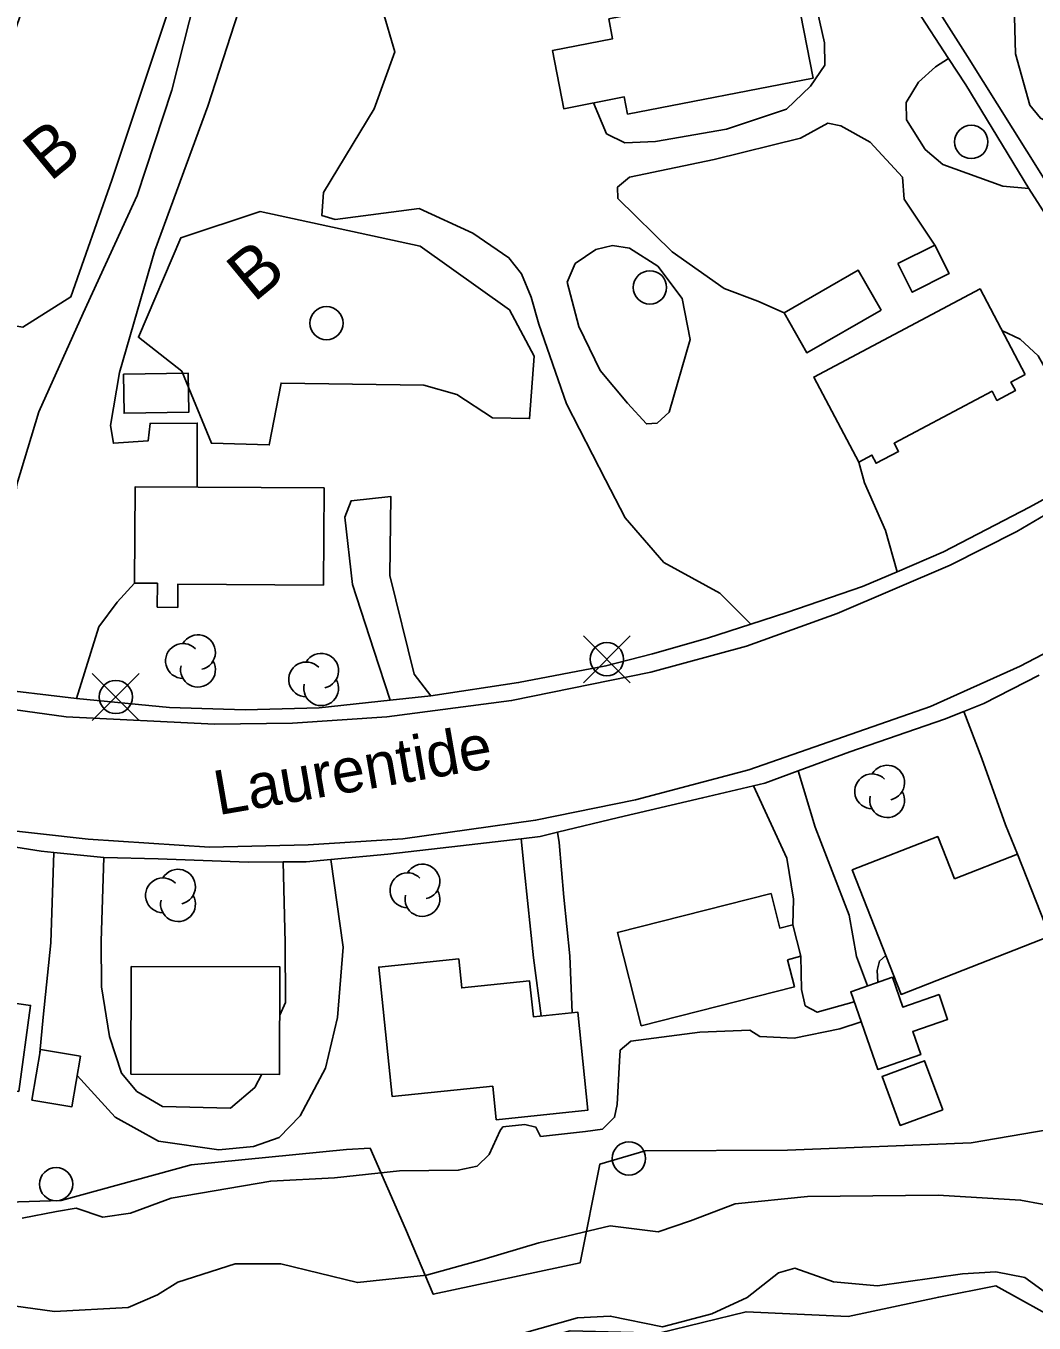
# Model space of a CAD drawing. Extents: x 347059 to 352153, y 6073752 to 6078601.
# Drawn here: x 348771.1 to 348862, y 6074348.3 to 6074465.1 of the extents above; entities that cross this region are included whole.
import ezdxf

# ---------------------------------------------------------------- set-up
doc = ezdxf.new("R2010")
doc.units = 0
for name, color, linetype in [('Level 19', 7, 'Continuous'), ('Level 2', 7, 'Continuous'), ('Level 21', 7, 'Continuous'), ('Level 22', 7, 'Continuous'), ('Level 31', 7, 'Continuous'), ('Level 36', 7, 'Continuous'), ('Level 4', 7, 'Continuous'), ('Level 44', 7, 'Continuous')]:
    doc.layers.add(name, color=color, linetype=linetype)

msp = doc.modelspace()

# ---------------------------------------------------------------- linework, layer by layer
at = {"layer": 'Level 19'}
for points in [[(348767.61, 6074405.52), (348768.93, 6074410.7), (348769.75, 6074418.56), (348770.34, 6074423.81), (348772.31, 6074430.38), (348776.32, 6074439.27), (348781.18, 6074449.85), (348784.3, 6074459.35), (348786.9, 6074469.69), (348789.29, 6074475.94), (348791.24, 6074483.88)], [(348838.96, 6074479.63), (348839.5, 6074478.19), (348840.93, 6074473.21), (348843.09, 6074463.63), (348843.12, 6074461.61), (348841.85, 6074459.71), (348839.66, 6074457.64), (348834.28, 6074455.83), (348827.86, 6074454.73), (348825.11, 6074454.61), (348823.47, 6074455.42), (348822.29, 6074458.2)], [(348903.21, 6074452.61), (348898.9, 6074457.29), (348893.63, 6074463.12), (348887.95, 6074467.63), (348883.19, 6074464.98), (348879.98, 6074463.79), (348874.86, 6074461.22), (348872.05, 6074459.46), (348865.53, 6074455.94), (348864.04, 6074456.12), (348862.55, 6074456.83), (348861.59, 6074457.99), (348860.3, 6074462.63), (348860.12, 6074469.35), (348860.79, 6074472.71)], [(348786.58, 6074423.58), (348786.58, 6074429.36), (348782.34, 6074429.33), (348782.16, 6074427.75), (348779.03, 6074427.54), (348778.78, 6074429.14), (348779.59, 6074433.92), (348782.76, 6074444.9), (348787.55, 6074457.92), (348791.33, 6074469.63)], [(348803.27, 6074466.6), (348804.4, 6074462.8), (348802.51, 6074457.66), (348797.97, 6074450.13), (348797.82, 6074448.05), (348799.01, 6074447.69), (348806.57, 6074448.69), (348811.4, 6074446.48), (348814.67, 6074444.25), (348815.8, 6074442.79), (348816.68, 6074440.71), (348817.36, 6074438.27), (348819.86, 6074431.09), (348823.37, 6074424.23), (348825.15, 6074420.82), (348828.63, 6074416.8), (348833.68, 6074414.04), (348836.45, 6074411.24)], [(348861.52, 6074450.49), (348859.17, 6074450.7), (348853.75, 6074452.64), (348852.16, 6074454.02), (348850.48, 6074456.68), (348850.46, 6074458.25), (348851.56, 6074460.08), (348853.11, 6074461.46), (348854.27, 6074462.21)], [(348839.45, 6074439.3), (348837.09, 6074440.33), (348834.05, 6074441.48), (348829.37, 6074444.78), (348824.49, 6074449.59), (348824.46, 6074450.62), (348825.52, 6074451.51), (348833.17, 6074453.11), (348840.93, 6074455.04), (348843.41, 6074456.37), (348844.58, 6074456.14), (348847.22, 6074454.67), (348850.12, 6074451.52), (348850.27, 6074449.54), (348853.03, 6074445.4)], [(348819.9, 6074442.06), (348820.97, 6074438.06), (348822.9, 6074434.1), (348825.34, 6074431.16), (348827.05, 6074429.28), (348828.03, 6074429.36), (348829.1, 6074430.33), (348830.99, 6074436.9), (348830.26, 6074440.59), (348828.07, 6074443.5), (348825.52, 6074445.13), (348823.99, 6074445.35), (348822.49, 6074445), (348820.62, 6074443.73), (348819.9, 6074442.06)], [(348859.09, 6074437.7), (348860.72, 6074436.92), (348862.34, 6074435.42), (348865.54, 6074429.74), (348867.91, 6074425.47)], [(348849.64, 6074415.96), (348848.59, 6074419.68), (348846.69, 6074423.96), (348846.18, 6074425.85)], [(348807.62, 6074404.77), (348806.13, 6074406.75), (348803.94, 6074415.62), (348804.04, 6074422.73), (348800.45, 6074422.36), (348799.87, 6074420.89), (348800.56, 6074414.82), (348802.48, 6074408.89), (348803.98, 6074404.38)], [(348775.69, 6074404.54), (348777.73, 6074411.01), (348779.36, 6074413.21), (348780.94, 6074414.95)], [(348855.65, 6074403.38), (348857.28, 6074399.13), (348859.4, 6074393.15), (348860.49, 6074390.53)], [(348840.74, 6074398.03), (348842.27, 6074392.94), (348845.31, 6074385.02), (348845.99, 6074381.3), (348846.97, 6074378.65)], [(348840.26, 6074384.16), (348840.3, 6074386.46), (348839.69, 6074390.17), (348836.71, 6074396.68)], [(348815.76, 6074391.91), (348816.08, 6074388.93), (348816.89, 6074381.17), (348817.57, 6074375.95)], [(348820.37, 6074376.24), (348820.14, 6074381.35), (348819.6, 6074386.64), (348819.18, 6074391.57), (348819.04, 6074392.49)], [(348773.66, 6074390.68), (348773.38, 6074382.52), (348772.71, 6074375.84), (348772.41, 6074372.63)], [(348775.77, 6074370.58), (348779.19, 6074366.82), (348783.08, 6074364.66), (348788.52, 6074363.88), (348791.65, 6074364.18), (348793.96, 6074364.99), (348795.85, 6074366.96), (348798.15, 6074371.23), (348799.21, 6074375.82), (348799.73, 6074382.14), (348798.61, 6074390.04)], [(348778.18, 6074390.21), (348777.92, 6074382.67), (348777.97, 6074378.56), (348778.67, 6074374.1), (348779.77, 6074370.79), (348781.13, 6074369.15), (348783.46, 6074367.79), (348789.57, 6074367.65), (348791.78, 6074369.5), (348792.41, 6074370.69)], [(348794.31, 6074389.82), (348794.51, 6074382.52), (348794.55, 6074377.16), (348794.01, 6074376.03)], [(348845.78, 6074377.21), (348842.44, 6074376.28), (348841.35, 6074376.87), (348841.03, 6074378.34), (348840.98, 6074381.32)]]:
    msp.add_lwpolyline(points, dxfattribs=at)
at = {"layer": 'Level 2'}
for points in [[(348860.74, 6074389.88), (348860.72, 6074389.87)], [(348848.62, 6074381.4), (348848.05, 6074380.89), (348847.83, 6074380.04), (348847.91, 6074378.98)], [(348846.4, 6074375.42), (348844.48, 6074374.77), (348840.37, 6074373.95), (348837.26, 6074374.08), (348836.37, 6074374.67), (348831.87, 6074374.49), (348825.64, 6074373.66), (348824.7, 6074372.87), (348824.62, 6074371.86), (348824.43, 6074367.96), (348824.19, 6074366.82), (348823.09, 6074365.76), (348821.55, 6074365.53), (348817.52, 6074365.09), (348817.09, 6074365.92), (348816.09, 6074366.16), (348814.12, 6074365.97), (348813.88, 6074365.63), (348812.9, 6074363.46), (348811.79, 6074362.4), (348810.1, 6074362.04), (348804.8, 6074362), (348798.95, 6074361.36), (348793.2, 6074361.07), (348784.23, 6074359.54), (348780.57, 6074358.19), (348778.07, 6074357.83), (348775.68, 6074358.62), (348773.91, 6074358.34), (348770.82, 6074357.74)], [(348912.02, 6074354.33), (348907.11, 6074355.41), (348904.58, 6074355.42), (348903.02, 6074355.05), (348899.24, 6074354), (348896.1, 6074352.03), (348893.13, 6074351.13), (348890.25, 6074351.38), (348888.9, 6074351.72), (348883.01, 6074354.93), (348877.78, 6074356.55), (348874.88, 6074357.32), (348866.62, 6074358.26), (348860.77, 6074359.36), (348853.34, 6074359.8), (348841.58, 6074359.67), (348835.06, 6074359.01), (348831.02, 6074357.48), (348828.11, 6074356.5), (348823.8, 6074357.03)], [(348768.27, 6074350.08), (348773.73, 6074349.31), (348780.36, 6074349.67), (348783, 6074350.82), (348784.84, 6074351.96), (348789.99, 6074353.62), (348794.12, 6074353.61), (348801.02, 6074351.92), (348807.24, 6074352.6), (348812.22, 6074353.98), (348817.36, 6074355.49), (348823.8, 6074357.03)]]:
    msp.add_lwpolyline(points, dxfattribs=at)
at = {"layer": 'Level 21'}
for points in [[(348767.35, 6074403.9), (348774.78, 6074402.9), (348788.15, 6074402.22), (348795.17, 6074402.32), (348803.67, 6074402.9), (348814.9, 6074404.35), (348827.45, 6074406.91), (348836.06, 6074409.25), (348844.24, 6074412.21), (348854.42, 6074416.55), (348860.44, 6074419.58), (348870.13, 6074425.31), (348877.31, 6074430.29), (348887.9, 6074438.38), (348896.05, 6074445.08), (348904.85, 6074452.18), (348914.51, 6074459.85), (348923.26, 6074466.91)], [(348767.86, 6074392.86), (348776.75, 6074391.88), (348787.7, 6074391.14), (348796.58, 6074391.36), (348805.12, 6074391.9), (348817.06, 6074393.57), (348826.08, 6074395.43), (348836.27, 6074398.12), (348844.82, 6074401.08), (348852.65, 6074403.82), (348860.72, 6074407.45), (348870.22, 6074412.42)]]:
    msp.add_lwpolyline(points, dxfattribs=at)
at = {"layer": 'Level 22'}
for points in [[(348852.05, 6074468.6), (348855.98, 6074462.39), (348862.73, 6074451.61), (348870.28, 6074439.32), (348875.67, 6074430.81), (348879.74, 6074433.85), (348886.12, 6074438.62), (348893.49, 6074444.82), (348895.77, 6074446.67), (348899.3, 6074449.55), (348903.21, 6074452.61), (348905.79, 6074454.64), (348912.74, 6074460.34), (348920.82, 6074466.76)], [(348867.35, 6074441.36), (348861.52, 6074450.49), (348855.82, 6074459.82), (348854.27, 6074462.21), (348851.41, 6074466.6)], [(348767.61, 6074405.52), (348775.69, 6074404.54), (348784.07, 6074403.74), (348790.91, 6074403.53), (348797.57, 6074403.7), (348803.98, 6074404.38), (348807.62, 6074404.77), (348815.53, 6074405.98), (348823.41, 6074407.48), (348827.59, 6074408.58), (348832.57, 6074409.98), (348836.45, 6074411.24), (348839.71, 6074412.29), (348846.53, 6074414.63), (348849.64, 6074415.96), (348853.82, 6074417.75), (348861.56, 6074421.77), (348866.54, 6074424.53)], [(348766.77, 6074391.69), (348772.52, 6074390.8), (348773.66, 6074390.68), (348778.18, 6074390.21), (348783.07, 6074390.09), (348791.17, 6074389.81), (348794.31, 6074389.82), (348796.39, 6074389.83), (348798.61, 6074390.04), (348803.76, 6074390.52), (348810.31, 6074391.28), (348815.76, 6074391.91), (348817.48, 6074392.11), (348819.04, 6074392.49), (348824.53, 6074393.81), (348832.11, 6074395.59), (348836.71, 6074396.68), (348837.73, 6074396.93), (348840.74, 6074398.03), (348845.37, 6074399.73), (348853.91, 6074402.69), (348855.65, 6074403.38), (348857.46, 6074404.1), (348862.44, 6074406.64)]]:
    msp.add_lwpolyline(points, dxfattribs=at)
at = {"layer": 'Level 31'}
for points in [[(348823.66, 6074465.78), (348840.4, 6074469.04), (348842.07, 6074460.44), (348825.35, 6074457.19), (348825.05, 6074458.74), (348819.61, 6074457.68), (348818.59, 6074462.92), (348824.01, 6074463.98), (348823.66, 6074465.78)], [(348849.71, 6074443.73), (348853.03, 6074445.4), (348854.33, 6074442.82), (348851, 6074441.15), (348849.71, 6074443.73)], [(348848.19, 6074439.52), (348841.5, 6074435.7), (348839.45, 6074439.3), (348846.14, 6074443.12), (348848.19, 6074439.52)], [(348861.19, 6074433.74), (348857.11, 6074441.44), (348842.13, 6074433.5), (348846.18, 6074425.85), (348847.37, 6074426.47), (348847.75, 6074425.74), (348849.77, 6074426.81), (348849.37, 6074427.54), (348858.19, 6074432.22), (348858.63, 6074431.4), (348860.3, 6074432.28), (348859.89, 6074433.05), (348861.19, 6074433.74)], [(348779.94, 6074433.77), (348785.77, 6074433.85), (348785.82, 6074430.33), (348779.99, 6074430.25), (348779.94, 6074433.77)], [(348782.98, 6074412.76), (348782.99, 6074414.93), (348780.94, 6074414.95), (348781, 6074423.62), (348798.01, 6074423.51), (348797.95, 6074414.76), (348784.84, 6074414.85), (348784.83, 6074412.75), (348782.98, 6074412.76)], [(348854.8, 6074388.3), (348860.49, 6074390.53), (348863.39, 6074383.13), (348850, 6074377.88), (348845.6, 6074389.1), (348853.3, 6074392.11), (348854.8, 6074388.3)], [(348839.77, 6074381.01), (348840.39, 6074378.56), (348826.59, 6074375.06), (348824.46, 6074383.47), (348838.28, 6074386.97), (348839.07, 6074383.86), (348840.26, 6074384.16), (348840.98, 6074381.32), (348839.77, 6074381.01)], [(348770.5, 6074369.13), (348756.59, 6074371.04), (348758.24, 6074383.07), (348766.17, 6074381.98), (348765.59, 6074377.72), (348771.57, 6074376.9), (348770.5, 6074369.13)], [(348780.63, 6074380.39), (348794.02, 6074380.37), (348794, 6074370.68), (348780.61, 6074370.71), (348780.63, 6074380.39)], [(348813.21, 6074369.63), (348804.14, 6074368.69), (348802.93, 6074380.34), (348810.14, 6074381.09), (348810.41, 6074378.47), (348816.53, 6074379.1), (348816.87, 6074375.88), (348820.87, 6074376.29), (348821.78, 6074367.46), (348813.53, 6074366.6), (348813.21, 6074369.63)], [(348853.42, 6074377.87), (348854.19, 6074375.63), (348851.05, 6074374.55), (348851.77, 6074372.47), (348847.89, 6074371.13), (348845.46, 6074378.13), (348849.22, 6074379.43), (348850.15, 6074376.74), (348853.42, 6074377.87)], [(348776.06, 6074372.32), (348775.29, 6074367.76), (348771.69, 6074368.37), (348772.46, 6074372.93), (348776.06, 6074372.32)], [(348853.75, 6074367.5), (348849.92, 6074366.08), (348848.29, 6074370.49), (348852.12, 6074371.91), (348853.75, 6074367.5)]]:
    msp.add_lwpolyline(points, dxfattribs=at)
at = {"layer": 'Level 36'}
for p, q in [((348825.6, 6074405.97), (348821.37, 6074410.2)), ((348821.37, 6074405.97), (348825.6, 6074410.2)), ((348781.36, 6074402.56), (348777.13, 6074406.79)), ((348777.13, 6074402.56), (348781.36, 6074406.79))]:
    msp.add_line(p, q, dxfattribs=at)
for centre in [(348856.32, 6074454.69), (348827.37, 6074441.58), (348798.23, 6074438.36), (348823.49, 6074408.09), (348779.25, 6074404.68), (348825.48, 6074363.11), (348773.87, 6074360.79)]:
    msp.add_circle(centre, 1.5, dxfattribs=at)
at = {"layer": 'Level 4'}
msp.add_lwpolyline([(348870.22, 6074346.86), (348864.88, 6074349.69), (348861.15, 6074352.37), (348858.54, 6074352.89), (348855.54, 6074352.71), (348847.88, 6074351.63), (348843.91, 6074351.99), (348840.42, 6074353.21), (348838.95, 6074352.81), (348836.14, 6074350.59), (348832.94, 6074349.11), (348828.5, 6074347.95), (348823.8, 6074348.91), (348820.84, 6074348.76), (348814.05, 6074346.82)], dxfattribs=at)
at = {"layer": 'Level 44'}
for points in [[(348786.48, 6074474.07), (348778.9, 6074451.24), (348775.2, 6074440.72), (348770.88, 6074437.99), (348766.7, 6074438.7), (348763.64, 6074443.83), (348765.43, 6074448.36), (348768.6, 6074460.24), (348772, 6074470.05), (348783.91, 6074478.25), (348786.46, 6074477.53), (348786.48, 6074474.07)], [(348807, 6074432.78), (348794.14, 6074432.96), (348793.07, 6074427.39), (348787.86, 6074427.54), (348785.18, 6074434.03), (348781.29, 6074437.09), (348785.1, 6074446.04), (348792.25, 6074448.43), (348806.66, 6074445.3), (348814.71, 6074439.55), (348816.95, 6074435.4), (348816.53, 6074429.77), (348813.2, 6074429.83), (348809.96, 6074431.93), (348807, 6074432.78)], [(348762.78, 6074358.96), (348774.32, 6074359.32), (348786.03, 6074362.53), (348800.02, 6074363.9), (348802.16, 6074364.03), (348805.34, 6074356.76), (348807.84, 6074350.87), (348821.08, 6074353.7), (348822.85, 6074362.59), (348826.95, 6074363.78), (348839.77, 6074363.85), (348856.3, 6074364.5), (348869.14, 6074366.7), (348884.31, 6074366.65), (348892.77, 6074365.63), (348899.61, 6074374.55), (348903.18, 6074378.9), (348905.07, 6074378.24), (348912.28, 6074365.19), (348924.29, 6074348.51), (348936.55, 6074339.12)], [(348879.92, 6074338.67), (348864.93, 6074348.08), (348858.54, 6074351.62), (348853.39, 6074350.61), (348845.23, 6074348.87), (348836.03, 6074349.29), (348828.18, 6074347.37), (348820.19, 6074347.59), (348806.69, 6074343.79), (348800.41, 6074342.13), (348791.83, 6074336.73), (348775.52, 6074333.59), (348750.39, 6074335.44)]]:
    msp.add_lwpolyline(points, dxfattribs=at)
for centre, start, end in [((348785.3, 6074407.93), 44.1154, 269.804), ((348786.65, 6074408.71), 282.2692, 149.7263), ((348797.75, 6074407.04), 282.2692, 149.7263), ((348786.65, 6074407.14), 166.9369, 29.6212), ((348796.4, 6074406.26), 44.1154, 269.804), ((348797.75, 6074405.47), 166.9369, 29.6212), ((348847.39, 6074396.18), 44.1154, 269.804), ((348848.74, 6074396.96), 282.2692, 149.7263), ((348848.74, 6074395.39), 166.9369, 29.6212), ((348806.87, 6074388.05), 282.2692, 149.7263), ((348783.5, 6074386.81), 44.1154, 269.804), ((348784.85, 6074387.59), 282.2692, 149.7263), ((348805.52, 6074387.27), 44.1154, 269.804), ((348806.87, 6074386.48), 166.9369, 29.6212), ((348784.85, 6074386.02), 166.9369, 29.6212)]:
    msp.add_arc(centre, 1.57, start, end, dxfattribs=at)

# ---------------------------------------------------------------- texts
at = {"layer": 'Level 21'}
msp.add_text('Laurentide', height=4, rotation=9.857, dxfattribs=at).set_placement((348788.47, 6074394.02))
at = {"layer": 'Level 44'}
for p in [(348773.33, 6074451.03), (348791.69, 6074440.16)]:
    msp.add_text('B', height=4.5, rotation=39.568, dxfattribs=at).set_placement(p)

doc.saveas('drawing.dxf')
